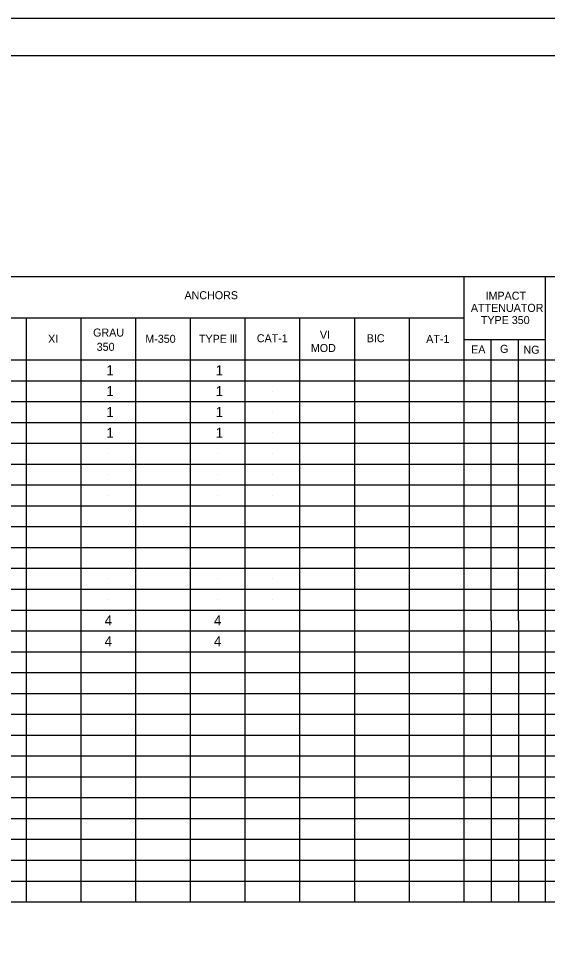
# Model space of a CAD drawing. Extents: x 578158 to 582505, y -54320 to -53220.
# Drawn here: x 579178 to 579495, y -53770 to -53220 of the extents above; entities that cross this region are included whole.
import ezdxf

# ---------------------------------------------------------------- set-up
doc = ezdxf.new("R2010")
doc.units = 0
for name, color, linetype in [('Old_Level_41', 7, 'Continuous'), ('Old_Level_44', 7, 'Continuous'), ('Sheet Plot Border Inside CELL', 7, 'Continuous'), ('Sheet Plot Border Outside CELL', 7, 'Continuous')]:
    doc.layers.add(name, color=color, linetype=linetype)

msp = doc.modelspace()

# ---------------------------------------------------------------- linework, layer by layer
at = {"layer": 'Old_Level_41'}
for p, q in [((578334.55, -53374.5), (579816.25, -53374.36)), ((579444.81, -53374.36), (579444.81, -53749.36)), ((579493.66, -53374.36), (579493.66, -53749.36)), ((579444.81, -53399.36), (578967.66, -53399.36)), ((579182.31, -53399.36), (579182.31, -53749.36)), ((579215.11, -53399.36), (579215.11, -53749.36)), ((579247.96, -53399.36), (579247.96, -53749.36)), ((579280.76, -53399.36), (579280.76, -53749.36)), ((579313.56, -53399.36), (579313.56, -53749.36)), ((579346.36, -53399.36), (579346.36, -53749.36)), ((579379.21, -53399.36), (579379.21, -53749.36)), ((579412.01, -53399.36), (579412.01, -53749.36)), ((579444.81, -53412.11), (579493.41, -53412.11)), ((579461.06, -53412.11), (579461.25, -53749.36)), ((579477.41, -53412.11), (579477.6, -53749.36)), ((578334.86, -53424.36), (579816.25, -53424.36)), ((578334.86, -53436.86), (579816.25, -53436.86)), ((578433.26, -53436.86), (579816.25, -53436.86)), ((579231.53, -53443.11), (579231.53, -53443.11)), ((579329.93, -53443.11), (579329.93, -53443.11)), ((578334.86, -53449.36), (579816.25, -53449.36)), ((578433.26, -53449.36), (579816.25, -53449.36)), ((579231.53, -53455.61), (579231.53, -53455.61)), ((579297.13, -53455.61), (579297.13, -53455.61)), ((579329.93, -53455.61), (579329.93, -53455.61)), ((578334.86, -53461.86), (579816.25, -53461.86)), ((578433.26, -53461.86), (579816.25, -53461.86)), ((579231.53, -53468.11), (579231.53, -53468.11)), ((579297.13, -53468.11), (579297.13, -53468.11)), ((579297.13, -53468.11), (579297.13, -53468.11)), ((579329.93, -53468.11), (579329.93, -53468.11)), ((578334.86, -53474.36), (579816.25, -53474.36)), ((578433.26, -53474.36), (579816.25, -53474.36)), ((579231.53, -53480.61), (579231.53, -53480.61)), ((579297.13, -53480.61), (579297.13, -53480.61)), ((579329.93, -53480.61), (579329.93, -53480.61)), ((578334.86, -53486.86), (579816.25, -53486.86)), ((578433.26, -53486.86), (579816.25, -53486.86)), ((579231.53, -53493.11), (579231.53, -53493.11)), ((579297.13, -53493.11), (579297.13, -53493.11)), ((579329.93, -53493.11), (579329.93, -53493.11)), ((578334.86, -53499.36), (579816.25, -53499.36)), ((578433.26, -53499.36), (579816.25, -53499.36)), ((579231.53, -53505.61), (579231.53, -53505.61)), ((579297.13, -53505.61), (579297.13, -53505.61)), ((579329.93, -53505.61), (579329.93, -53505.61)), ((578334.86, -53511.86), (579816.25, -53511.86)), ((578433.26, -53511.86), (579816.25, -53511.86)), ((578334.86, -53524.36), (579816.25, -53524.36)), ((578433.26, -53524.36), (579816.25, -53524.36)), ((578334.86, -53536.86), (579816.25, -53536.86)), ((578433.26, -53536.86), (579816.25, -53536.86)), ((578334.86, -53549.36), (579816.25, -53549.36)), ((578433.26, -53549.36), (579816.25, -53549.36)), ((579231.53, -53555.61), (579231.53, -53555.61)), ((579297.13, -53555.61), (579297.13, -53555.61)), ((579329.93, -53555.61), (579329.93, -53555.61)), ((578334.86, -53561.86), (579816.25, -53561.86)), ((578433.26, -53561.86), (579816.25, -53561.86)), ((579231.53, -53568.11), (579231.53, -53568.11)), ((579231.53, -53568.11), (579231.53, -53568.11)), ((579297.13, -53568.11), (579297.13, -53568.11)), ((579297.13, -53568.11), (579297.13, -53568.11)), ((579329.93, -53568.11), (579329.93, -53568.11)), ((579329.93, -53568.11), (579329.93, -53568.11)), ((578334.86, -53574.36), (579816.25, -53574.36)), ((579231.53, -53580.61), (579231.53, -53580.61)), ((579297.13, -53580.61), (579297.13, -53580.61)), ((578334.86, -53586.86), (579816.25, -53586.86)), ((579231.53, -53593.11), (579231.53, -53593.11)), ((579231.53, -53593.11), (579231.53, -53593.11)), ((579297.13, -53593.11), (579297.13, -53593.11)), ((579297.13, -53593.11), (579297.13, -53593.11)), ((578334.86, -53599.36), (579816.25, -53599.36)), ((578334.86, -53611.86), (579816.25, -53611.86)), ((578334.86, -53624.36), (579816.25, -53624.36)), ((578334.86, -53636.86), (579816.25, -53636.86)), ((578334.86, -53649.36), (579816.25, -53649.36)), ((578334.86, -53661.86), (579816.25, -53661.86)), ((578334.86, -53674.36), (579816.25, -53674.36)), ((578334.86, -53686.86), (579816.25, -53686.86)), ((578334.86, -53699.36), (579816.25, -53699.36)), ((578334.86, -53711.86), (579816.25, -53711.86)), ((578334.86, -53724.36), (579816.25, -53724.36)), ((578334.86, -53736.86), (579816.25, -53736.86)), ((578334.86, -53749.36), (579816.25, -53749.36))]:
    msp.add_line(p, q, dxfattribs=at)
at = {"layer": 'Sheet Plot Border Inside CELL'}
msp.add_lwpolyline([(578171.44, -54297.11), (579837.44, -54297.11), (579837.44, -53242.11), (578171.44, -53242.11)], close=True, dxfattribs=at)
at = {"layer": 'Sheet Plot Border Outside CELL'}
msp.add_lwpolyline([(578158.44, -54319.61), (579841.94, -54319.61), (579841.94, -53219.61), (578158.44, -53219.61)], close=True, dxfattribs=at)

# ---------------------------------------------------------------- texts
at = {"layer": 'Old_Level_41'}
for s, height, p in [('ANCHORS', 4.8, (579277.31, -53388.01)), ('IMPACT', 4.8, (579457.91, -53388.31)), ('ATTENUATOR', 4.8, (579449.11, -53395.61)), ('TYPE 350', 4.8, (579455.11, -53402.91)), ('EA', 4.8, (579449.26, -53420.51)), ('G', 4.8, (579466.61, -53420.16)), ('NG', 4.8, (579480.66, -53420.71)), ('1', 6, (579230.44, -53433.61)), ('1', 6, (579296.04, -53433.61)), ('1', 6, (579230.44, -53446.11)), ('1', 6, (579296.04, -53446.11)), ('1', 6, (579230.44, -53458.61)), ('1', 6, (579296.04, -53458.61)), ('1', 6, (579230.44, -53471.11)), ('1', 6, (579296.04, -53471.11)), ('4', 6, (579229.38, -53583.61)), ('4', 6, (579294.98, -53583.61)), ('4', 6, (579229.38, -53596.11)), ('4', 6, (579294.98, -53596.11))]:
    msp.add_text(s, height=height, dxfattribs=at).set_placement(p)
at = {"layer": 'Old_Level_44'}
for s, p in [('XI', (579195.51, -53414.16)), ('GRAU', (579222.51, -53410.41)), ('M-350', (579253.81, -53414.16)), ('TYPE lll', (579285.99, -53414.16)), ('CAT-1', (579320.71, -53413.81)), ('VI', (579358.56, -53411.76)), ('BIC', (579386.66, -53413.81)), ('AT-1', (579422.31, -53414.21)), ('350', (579224.66, -53418.96)), ('MOD', (579353.11, -53419.66))]:
    msp.add_text(s, height=4.8, dxfattribs=at).set_placement(p)

doc.saveas('drawing.dxf')
